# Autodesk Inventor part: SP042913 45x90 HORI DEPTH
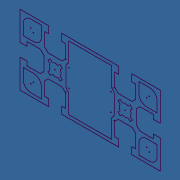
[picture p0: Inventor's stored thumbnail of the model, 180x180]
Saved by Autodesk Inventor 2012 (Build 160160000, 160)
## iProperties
Created: 2013-04
Part Number: SP042913 45x90 HORI DEPTH
Material: Aluminum-6061
Description: PROFILE 45X90 F
Document SubType Name: Modeling
Designer: Admin
Stock Number: 20.1032 PROFILE 45X90 F
Density: 2.71 g/cm^3
FINISH: CLEAR ANODIZED
Author: Admin
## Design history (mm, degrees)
sketch "Sketch1"
  geometry: L1 (43, -8.8)-(43, -15.5) reference; L2 (38, -20.5)-(31.3, -20.5) reference; L3 (31.3, -20.5)-(31.3, -13.8) reference; L4 (36.3, -8.8)-(43, -8.8) reference; L5 (-43, 8.8)-(-43, 15.5) reference; L6 (-38, 20.5)-(-31.3, 20.5) reference; L7 (-31.3, 20.5)-(-31.3, 13.8) reference; L8 (-36.3, 8.8)-(-43, 8.8) reference; L9 (43, 15.5)-(43, 8.8) reference; L10 (43, 8.8)-(36.3, 8.8) reference; L11 (31.3, 13.8)-(31.3, 20.5) reference; L12 (31.3, 20.5)-(38, 20.5) reference; L13 (-43, -15.5)-(-43, -8.8) reference; L14 (-43, -8.8)-(-36.3, -8.8) reference; L15 (-31.3, -13.8)-(-31.3, -20.5) reference; L16 (-31.3, -20.5)-(-38, -20.5) reference; L17 (-25.682, -4.596)-(-27.096, -3.182) reference; L18 (-27.096, -3.182)-(-25.763, -1.849) reference; L19 (-25.763, 1.849)-(-27.096, 3.182) reference; L20 (-27.096, 3.182)-(-25.682, 4.596) reference; L21 (-25.682, 4.596)-(-24.349, 3.263) reference; L22 (-20.651, 3.263)-(-19.318, 4.596) reference; L23 (-19.318, 4.596)-(-17.904, 3.182) reference; L24 (-17.904, 3.182)-(-19.237, 1.849) reference; L25 (-19.237, -1.849)-(-17.904, -3.182) reference; L26 (-17.904, -3.182)-(-19.318, -4.596) reference; L27 (-19.318, -4.596)-(-20.651, -3.263) reference; L28 (-24.349, -3.263)-(-25.682, -4.596) reference; L29 (19.318, -4.596)-(17.904, -3.182) reference; L30 (17.904, -3.182)-(19.237, -1.849) reference; L31 (19.237, 1.849)-(17.904, 3.182) reference; L32 (17.904, 3.182)-(19.318, 4.596) reference; L33 (19.318, 4.596)-(20.651, 3.263) reference; L34 (24.349, 3.263)-(25.682, 4.596) reference; L35 (25.682, 4.596)-(27.096, 3.182) reference; L36 (27.096, 3.182)-(25.763, 1.849) reference; L37 (25.763, -1.849)-(27.096, -3.182) reference; L38 (27.096, -3.182)-(25.682, -4.596) reference; L39 (25.682, -4.596)-(24.349, -3.263) reference; L40 (20.651, -3.263)-(19.318, -4.596) reference; L41 (-14.286, -7.786)-(-14.914, -7.157) reference; L42 (-15.5, -5.743)-(-15.5, 5.743) reference; L43 (-14.914, 7.157)-(-14.286, 7.786) reference; L44 (-13.7, 9.2)-(-13.7, 20.5) reference; L45 (-13.7, 20.5)-(13.7, 20.5) reference; L46 (13.7, 20.5)-(13.7, 9.2) reference; L47 (14.286, 7.786)-(14.914, 7.157) reference; L48 (15.5, 5.743)-(15.5, -5.743) reference; L49 (14.914, -7.157)-(14.286, -7.786) reference; L50 (13.7, -9.2)-(13.7, -20.5) reference; L51 (13.7, -20.5)-(-13.7, -20.5) reference; L52 (-13.7, -20.5)-(-13.7, -9.2) reference; L53 (26.6, 22.5)-(26.6, 18) reference; L54 (29.3, 18)-(29.3, 9.5) reference; L55 (29.3, 9.5)-(27, 7.2) reference; L56 (27, 7.2)-(18, 7.2) reference; L57 (18, 7.2)-(15.7, 9.5) reference; L58 (15.7, 9.5)-(15.7, 18) reference; L59 (15.7, 18)-(17.9, 18) reference; L60 (18.4, 18)-(18.4, 22.5) reference; L61 (-18.4, 22.5)-(-18.4, 18) reference; L62 (-15.7, 18)-(-15.7, 9.5) reference; L63 (-15.7, 9.5)-(-18, 7.2) reference; L64 (-18, 7.2)-(-27, 7.2) reference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; A1 r 5 centre (38, -15.5) between (38, -20.5) and (43, -15.5) reference; A2 r 5 centre (36.3, -13.8) between (36.3, -8.8) and (31.3, -13.8) reference; A3 r 5 centre (-38, 15.5) between (-38, 20.5) and (-43, 15.5) reference; A4 r 5 centre (-36.3, 13.8) between (-36.3, 8.8) and (-31.3, 13.8) reference; A5 r 5 centre (36.3, 13.8) between (31.3, 13.8) and (36.3, 8.8) reference; A6 r 5 centre (38, 15.5) between (43, 15.5) and (38, 20.5) reference; A7 r 5 centre (-36.3, -13.8) between (-31.3, -13.8) and (-36.3, -8.8) reference; A8 r 5 centre (-38, -15.5) between (-43, -15.5) and (-38, -20.5) reference; A9 r 3.75 centre (-22.5, 0) between (-24.16, -3.362) and (-20.84, -3.362) reference; A10 r 3.75 centre (22.5, 0) between (25.862, -1.66) and (25.862, 1.66) reference; A11 r 2 centre (-15.7, -9.2) between (-13.7, -9.2) and (-14.286, -7.786) reference; A12 r 2 centre (-13.5, -5.743) between (-15.5, -5.743) and (-14.914, -7.157) reference; A13 r 2 centre (-13.5, 5.743) between (-14.914, 7.157) and (-15.5, 5.743) reference; A14 r 2 centre (-15.7, 9.2) between (-14.286, 7.786) and (-13.7, 9.2) reference; A15 r 2 centre (15.7, 9.2) between (13.7, 9.2) and (14.286, 7.786) reference; A16 r 2 centre (13.5, 5.743) between (15.5, 5.743) and (14.914, 7.157) reference; A17 r 2 centre (13.5, -5.743) between (14.914, -7.157) and (15.5, -5.743) reference; A18 r 2 centre (15.7, -9.2) between (14.286, -7.786) and (13.7, -9.2) reference; A19 r 3.75 centre (-22.5, 0) between (-25.763, 1.849) and (-25.862, 1.66) reference; A20 r 3.75 centre (-22.5, 0) between (-25.862, 1.66) and (-25.763, -1.849) reference; A21 r 3.75 centre (-22.5, 0) between (-24.349, -3.263) and (-24.16, -3.362) reference; A22 r 3.75 centre (-22.5, 0) between (-19.138, 1.66) and (-19.237, 1.849) reference; A23 r 3.75 centre (-22.5, 0) between (-20.651, 3.263) and (-24.349, 3.263) reference; A24 r 3.75 centre (-22.5, 0) between (-20.84, -3.362) and (-20.651, -3.263) reference; A25 r 3.75 centre (-22.5, 0) between (-19.237, -1.849) and (-19.138, 1.66) reference; A26 r 3.75 centre (22.5, 0) between (20.84, 3.362) and (20.651, 3.263) reference; A27 r 3.75 centre (22.5, 0) between (19.237, 1.849) and (19.237, -1.849) reference; A28 r 3.75 centre (22.5, 0) between (20.651, -3.263) and (20.84, -3.362) reference; A29 r 3.75 centre (22.5, 0) between (20.84, -3.362) and (24.349, -3.263) reference; A30 r 3.75 centre (22.5, 0) between (25.763, -1.849) and (25.862, -1.66) reference; A31 r 3.75 centre (22.5, 0) between (25.862, 1.66) and (25.763, 1.849) reference; A32 r 3.75 centre (22.5, 0) between (24.349, 3.263) and (20.84, 3.362) reference
  constraints: 258 end point, 64 point on circle, 40 horizontal, 37 vertical, 32 centre point, 2 point on line, 269 other
extrude "Extrusion1" new body sketch "Sketch1" stored distance "d0" = 773.6 (computed from DEPTH, TOP_OVERHANG); taper "d1" = 0 deg
body "Solid1"
other parameters: "Height" = 1066.8 [user parameter], "Width" = 1828.8 [user parameter], "DEPTH" = 914.4 [user parameter; used in 1 equation term], "LOWER_INSET" = 203.2 [user parameter], "TABLE_TOP_THICKNESS" = 12.7 [user parameter], "LEVELER_HEIGHT" = 44.45 [user parameter], "TOP_OVERHANG" = 25.4 [user parameter; used in 1 equation term]
